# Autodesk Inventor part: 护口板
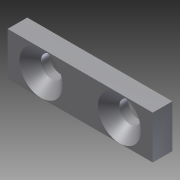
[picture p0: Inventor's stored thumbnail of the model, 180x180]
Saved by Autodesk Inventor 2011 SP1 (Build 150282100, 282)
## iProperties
Created: 2013-11
Part Number: 护口板
Document SubType Name: Modeling
Designer: Administrator
Density: 1 g/cm^3
Author: Administrator
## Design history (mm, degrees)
sketch "草图1"
  geometry: L1 (-37, 5)-(37, 5); L2 (37, 5)-(37, -5); L3 (37, -5)-(-37, -5); L4 (-37, -5)-(-37, 5); 3 further points
  constraints: 8 end point, 2 midpoint, 2 parallel, 1 horizontal, 1 horizontal alignment, 1 perpendicular, 1 vertical alignment
  dimensions: "d0" = 74 distance of L1.start L1.end; "d1" = 10 distance of L3.end L1.start
extrude "拉伸1" new body sketch "草图1" distance "d2" = 22; taper "d3" = 0 deg
hole "Hole1" diameter "d6" = 11; stored, may be unused: countersink angle "d10" = 90 deg, drill point angle "d12" = 0 deg; dims "d4" = 17, "d5" = 11, "d7" = 6, "d8" = 22, "d9" = 2, "d11" = 8
mirror "镜像1"
node "实体1"
